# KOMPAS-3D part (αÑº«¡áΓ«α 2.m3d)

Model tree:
1. Эскиз:1
2. Операция выдавливания:1
     Толщина стенки 1 = 2; Толщина стенки 2 = 8; Расстояние 1 = 1
3. Эскиз:3
4. Операция выдавливания:2
     Толщина стенки 1 = 2; Толщина стенки 2 = 6; Расстояние 1 = 5
5. Эскиз:4
6. Операция выдавливания:3
     Толщина стенки 1 = 2; Толщина стенки 2 = 6; Расстояние 1 = 1
7. Эскиз:5
8. Эскиз:6
9. Операция выдавливания:4
     Толщина стенки 1 = 2; Толщина стенки 2 = 2.5; Расстояние 1 = 50
10. Эскиз:7
11. Вырезать элемент выдавливания:1
     Толщина стенки 2 = 1.5; Расстояние 1 = 40
12. Эскиз:8
13. Операция выдавливания:5
     Толщина стенки 1 = 2; Толщина стенки 2 = 2.5; Расстояние 1 = 50
14. Эскиз:9
15. Вырезать элемент выдавливания:2
     Толщина стенки 2 = 1.5; Расстояние 1 = 40
16. Эскиз:10
17. Операция выдавливания:6
     Толщина стенки 1 = 2; Толщина стенки 2 = 2.5; Расстояние 1 = 10
18. Эскиз:11
19. Операция выдавливания:7
     Толщина стенки 1 = 2; Толщина стенки 2 = 6; Расстояние 1 = 1
20. Эскиз:12
21. Операция выдавливания:8
     Толщина стенки 1 = 2; Толщина стенки 2 = 6; Расстояние 1 = 5
22. Эскиз:13
23. Операция выдавливания:9
     Толщина стенки 1 = 2; Толщина стенки 2 = 8; Расстояние 1 = 1
24. Эскиз:14
25. Вырезать элемент выдавливания:3
     Толщина стенки 2 = 1.5; Расстояние 1 = 23
26. Эскиз:15
27. Вырезать элемент выдавливания:4
     Толщина стенки 2 = 1.5; Расстояние 1 = 1
28. Эскиз:16
29. Вырезать элемент выдавливания:5
     Расстояние 1 = 150
30. Эскиз:18
31. Операция выдавливания:11
     Толщина стенки 1 = 8; Толщина стенки 2 = 8; Расстояние 1 = 10; Расстояние 2 = 0.4
